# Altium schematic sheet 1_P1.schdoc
size 309 x 223 mm; Symbol: Sheet-Symbol_A4; Device: Sheet-Symbol_A4; Company: 嘉立创EDA; Version: V1.0; Page Size: A4; @Project Name: Magnetic robot_hkust_bi; @Page Count: 1; @Update Date: 2025-07-18; @Create Date: 2025-06-04; @Schematic Name: Schematic4; @Page No: 1; @Page Name: P1; @Board Name: Positioning tag; @Create Time: 22:55:14; @Update Time: 14:32:23
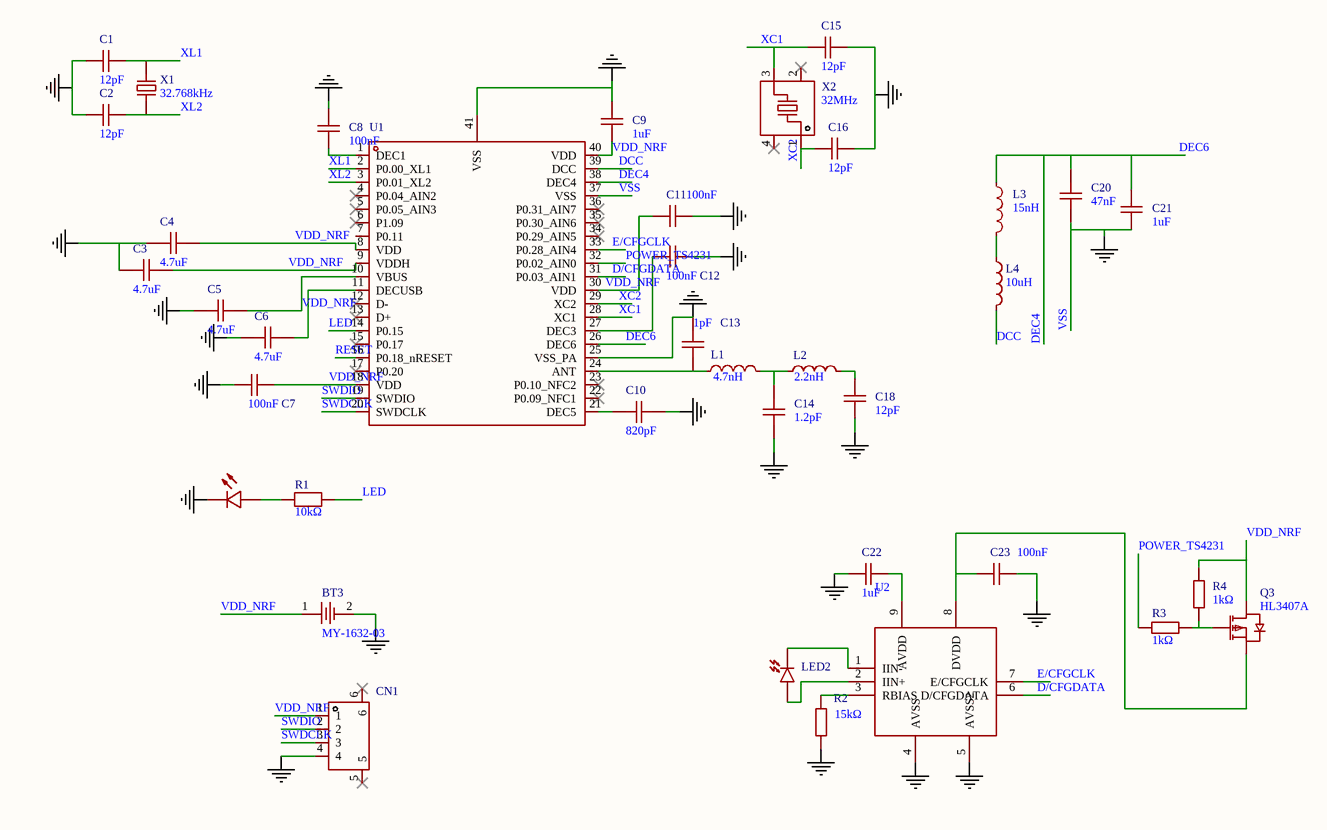
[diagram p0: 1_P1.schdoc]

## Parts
BT3  MY-1632-03  [BAT-SMD_MY-1632-03]
C1  12pF  [C0402]
C2  12pF  [C0402]
C3  4.7uF  [C0201]
C4  4.7uF  [C0201]
C5  4.7uF  [C0201]
C6  4.7uF  [C0201]
C7  100nF  [C0201]
C8  100nF  [C0201]
C9  1uF  [C0201]
C10  820pF  [C0402]
C11  100nF  [C0201]
C12  100nF  [C0201]
C13  1pF  [C0201]
C14  1.2pF  [C0201]
C15  12pF  [C0402]
C16  12pF  [C0402]
C18  12pF  [C0402]
C20  47nF  [C0201]
C21  1uF  [C0201]
C22  1uF  [C0201]
C23  100nF  [C0201]
CN1  1.0-4PWB  [CONN-SMD_4P-P1.00_DEALON_1.0-4PWB]  (value not drawn)
L1  4.7nH  [IND-SMD_L1.0-W0.6]
L2  2.2nH  [IND-SMD_L1.0-W0.6]
L3  15nH  [IND-SMD_L1.0-W0.5-2]
L4  10uH  [IND-SMD_L2.5-W2.0]
LED1  NCD0603G1  [LED0603-RD_1]  (value not drawn)
LED2  VBPW34S  [SENSOR-SMD_L4.4-W3.9]  (value not drawn)
Q3  HL3407A  [SOT-23-3_L2.9-W1.3-P1.90-LS2.4-BL-1]
R1  10kΩ  [R0201]
R2  15kΩ  [R0402]
R3  1kΩ  [R0201]
R4  1kΩ  [R0201]
U1  nRF52833-QDAA-R  [QFN-40_L5.0-W5.0-P0.40-TL-EP3.6]  (value not drawn)
U2  (no value)  [TS4231]
X1  32.768kHz  [OSC-SMD_L3.2-W1.5]
X2  32MHz  [CRYSTAL-SMD_4P-L2.0-W1.6-BL-2]

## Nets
VSS: BT3.2 C1.1 C2.1 C3.2 C4.2 C5.2 C6.2 C7.1 C8.2 C9.2 C10.2 C11.2 C12.2 C13.2 C14.1 C15.2 C16.2 C18.1 C20.1 C21.1 C22.2 C23.2 CN1.4 LED1.1(K) R2.1 U1.25(VSS_PA) U1.37(VSS) U1.41(VSS) U2.4(AVSS) U2.5(AVSS2)  [also labelled GND]
D/CFGDATA: U1.31(P0.03_AIN1) U2.6(D/CFGDATA)
DCC: L4.2 U1.39(DCC)
DEC4: C20.2 C21.2 L3.2 U1.26(DEC6) U1.38(DEC4)  [also labelled DEC6]
E/CFGCLK: U1.33(P0.28_AIN4) U2.7(E/CFGCLK)
LED: R1.1 U1.14(P0.15)
POWER_TS4231: R3.1 U1.32(P0.02_AIN0)
RESET: U1.16(P0.18_nRESET)
SWDCLK: CN1.3 U1.20(SWDCLK)
SWDIO: CN1.2 U1.19(SWDIO)
VDD_NRF: BT3.1 C3.1 C4.1 C5.1 C7.2 C9.1 C11.1 CN1.1 Q3.3(D) R4.2 U1.8(VDD) U1.9(VDDH) U1.10(VBUS) U1.18(VDD) U1.30(VDD) U1.40(VDD)
XC1: C15.1 U1.28(XC1) X2.3
XC2: C16.1 U1.29(XC2) X2.1
XL1: C1.2 U1.2(P0.00_XL1) X1.2
XL2: C2.2 U1.3(P0.01_XL2) X1.1
NetC6_1: C6.1 U1.11(DECUSB)
NetC8_1: C8.1 U1.1(DEC1)
NetC10_1: C10.1 U1.21(DEC5)
NetC12_1: C12.1 U1.27(DEC3)
NetC13_1: C13.1 L1.1 U1.24(ANT)
NetC14_2: C14.2 L1.2 L2.1
NetC18_2: C18.2 L2.2
NetC22_1: C22.1 U2.9(AVDD)
NetC23_1: C23.1 Q3.2(S) U2.8(DVDD)
NetL3_1: L3.1 L4.1
NetLED1_2: LED1.2(A) R1.2
NetLED2_1: LED2.1(A) U2.2(IIN+)
NetLED2_2: LED2.2(C) U2.1(IIN-)
NetQ3_1: Q3.1(G) R3.2 R4.1
NetR2_2: R2.2 U2.3(RBIAS)

Not connected (* = marked no-connect by the designer): CN1 5* 6*; U1 4(P0.04_AIN2)* 5(P0.05_AIN3)* 6(P1.09)* 7(P0.11) 12(D-)* 13(D+)* 15(P0.17)* 17(P0.20)* 22(P0.09_NFC1)* 23(P0.10_NFC2)* 34(P0.29_AIN5)* 35(P0.30_AIN6)* 36(P0.31_AIN7)*; X2 2(GND)* 4(GND)*

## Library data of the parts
BT3 = MY-1632-03: Manufacturer: MYOUNG(美阳); Add into BOM: yes; Connector Type: 电池扣; Battery Type: CR1632
C1 C2 C15 C16 C18 = GRM1555C1H120JA01D: Manufacturer: muRata(村田); Add into BOM: yes; Tolerance: ±5%; Voltage Rating: 50V; Temperature Coefficient: C0G
C3-C6 = GRM035R60J475ME15D: Manufacturer: muRata(村田); Add into BOM: yes; Tolerance: ±20%; Voltage Rating: 6.3V; Temperature Coefficient: X5R
C7 C8 C11 C12 C23 = GRM033R61E104KE14D: Manufacturer: muRata(村田); Add into BOM: yes; Tolerance: ±10%; Voltage Rating: 25V; Temperature Coefficient: X5R
C9 C21 C22 = GRM033R61A105ME44D: Manufacturer: muRata(村田); Add into BOM: yes; Tolerance: ±20%; Voltage Rated: 10V; Temperature Coefficient: X5R
C10 = CC0402KRX7R9BB821: Manufacturer: YAGEO(国巨); Add into BOM: yes; Tolerance: ±10%; Voltage Rated: 50V; Temperature Coefficient: X7R
C13 = GRM0335C1H1R0BA01D: Manufacturer: muRata(村田); Add into BOM: yes; Voltage Rating: 50V; Temperature Coefficient: C0G
C14 = GRM0335C1H1R2BA01D: Manufacturer: muRata(村田); Add into BOM: yes; Voltage Rated: 50V; Temperature Coefficient: C0G
C20 = CGA0201X5R473K160ET: Manufacturer: HRE(芯声); Add into BOM: yes; Tolerance: ±10%; Voltage Rating: 16V; Temperature Coefficient: X5R
CN1 = 1.0-4PWB: Manufacturer: DEALON(德艺隆); Add into BOM: yes; Pins Structure: 1x4P; Pitch: 1mm; Reference Series: SH; Number of PINs Per Row: 4; Current Rating: 1A; Voltage Rating: 50V; Supplementary Features: 辅助焊脚; Z-Height of the Board: 2.9mm; X-Length of Bottom Edge on Board (Spacing Line): 6mm; Y-Width of Bottom Edge on Board: 5.03mm
L1 = LQW15AN4N7B00D: Manufacturer: muRata(村田); Add into BOM: yes; Rated Current: 750mA; DC Resistance (DCR): 70mΩ
L2 = LQW15AN2N2B80D: Manufacturer: muRata(村田); Add into BOM: yes; Rated Current: 2.53A; DC Resistance (DCR): 22mΩ
L3 = LQW15AN15NG00D: Manufacturer: muRata(村田); Add into BOM: yes; Tolerance: ±2%; Rated Current: 460mA; DC Resistance (DCR): 160mΩ
L4 = FTC252012S100MBCA: Manufacturer: cjiang(长江微电); Add into BOM: yes; Tolerance: ±20%; Rated Current: 1.2A; Saturation Current (Isat): 1.6A; DC Resistance (DCR): 330mΩ; Type: 一体成型电感
LED1 = NCD0603G1: Manufacturer: 国星光电; Symbol: FC-D1608UGK-520D10; Add into BOM: yes; Illumination Color: 翠绿色; Voltage - Forward(Vf): 2.6V~3.6V; Power(Watts): 72mW; Forward Current: 20mA; Wavelength - Dominant: 515nm~530nm; Luminous Intensity: 330mcd~900mcd; Viewing Angle: 130°
LED2 = VBPW34S: Manufacturer: VISHAY(威世); Add into BOM: yes; DC Reverse Voltage: 60V; Peak  Wavelength: 940nm; Spectral Range: 430nm~1100nm; Current Dark: 2nA
Q3 = HL3407A: Manufacturer: 宏嘉诚; Add into BOM: yes; Drain to Source Voltage: 30V; Current - Continuous Drain(Id): 4.1A; RDS(on): 68mΩ@4.5V; Pd - Power Dissipation: 1.2W; Gate Threshold Voltage (Vgs(th)@Id): 2.4V@250uA; Gate Charge(Qg): 12nC@10V; Input Capacitance(Ciss): 572pF; Reverse Transfer Capacitance (Crss@Vds): 70pF@15V
R1 = 0201WMF1002TEE: Manufacturer: UNI-ROYAL(厚声); Add into BOM: yes; Tolerance: ±1%; Power(Watts): 50mW; Overload Voltage (Max): 25V; Temperature Coefficient: ±200ppm/℃
R2 = 0402WGF1502TCE: Manufacturer: UNI-ROYAL(厚声); Add into BOM: yes; Tolerance: ±1%; Power(Watts): 62.5mW; Overload Voltage (Max): 50V; Temperature Coefficient: ±100ppm/
R3 R4 = 0201WMF1001TEE: Manufacturer: UNI-ROYAL(厚声); Add into BOM: yes; Tolerance: ±1%; Power(Watts): 50mW; Overload Voltage (Max): 25V; Temperature Coefficient: ±200ppm/℃
U1 = nRF52833-QDAA-R: Manufacturer: NORDIC; Add into BOM: yes
U2 = TS4231: Add into BOM: yes
X1 = X321532768KGD2SI: Manufacturer: YXC(扬兴晶振); Add into BOM: yes; Crystal Type: 贴片晶振; Normal temperature Frequency Tolerance: ±20ppm; External load capacitor: 12.5pF
X2 = X201632MOB4SI: Manufacturer: YXC(扬兴晶振); Add into BOM: yes; Normal temperature Frequency Tolerance: ±10ppm; Load Capacitance: 12pF; Frequency Stability: ±20ppm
